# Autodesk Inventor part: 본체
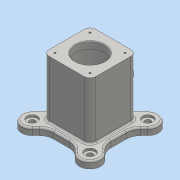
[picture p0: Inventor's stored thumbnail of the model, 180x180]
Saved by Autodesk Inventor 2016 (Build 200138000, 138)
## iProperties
Created: 2019-11
Part Number: 본체
Material: 일반
Document SubType Name: Modeling
Designer: user
Density: 1 g/cm^3
Appearance: 기본값
Author: user
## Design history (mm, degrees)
sketch "스케치2"
  geometry: L1 (-49, 49)-(49, 49); L2 (49, 49)-(49, -49); L3 (49, -49)-(-49, -49); L4 (-49, -49)-(-49, 49); L5 (-49, 49)-(49, -49); L6 (49, 49)-(-49, -49); L7 (49.497, -49.497)-(-49.497, 49.497); L8 (62.225, -36.77)-(-36.77, 62.225); L9 (-62.225, 36.77)-(36.77, -62.225); L10 (-49.497, -49.497)-(49.497, 49.497); L11 (-36.77, -62.225)-(62.225, 36.77); L12 (36.77, 62.225)-(-62.225, -36.77); A1 r 70 centre (0, 0) between (-49.497, 49.497) and (49.497, 49.497); A2 r 18 centre (49.497, -49.497) between (36.77, -62.225) and (62.225, -36.77); A3 r 18 centre (-49.497, 49.497) between (-36.77, 62.225) and (-62.225, 36.77); A4 r 18 centre (-49.497, -49.497) between (-62.225, -36.77) and (-36.77, -62.225); A5 r 18 centre (49.497, 49.497) between (62.225, 36.77) and (36.77, 62.225); 1 further point
  constraints: 28 end point, 10 point on circle, 8 tangent, 5 centre point, 4 midpoint, 4 parallel, 2 point on line, 1 coincident, 1 horizontal, 1 perpendicular
  dimensions: "d5" = 98 distance of L1.start L1.end; "d6" = 98 distance of L3.end L1.start; "d7" = 140 diameter of A1; "d8" = 36 diameter of A3; "d9" = 36 diameter of A5
extrude "돌출1" new body sketch "스케치2" distance "d10" = 12; taper "d11" = 0 deg
sketch "스케치3"
  geometry: L1 (-40, 40)-(40, 40); L2 (40, 40)-(40, -40); L3 (40, -40)-(-40, -40); L4 (-40, -40)-(-40, 40); L5 (-40, 40)-(40, -40); L6 (40, 40)-(-40, -40); 1 further point
  constraints: 12 end point, 2 midpoint, 2 parallel, 1 horizontal, 1 perpendicular
  dimensions: "d12" = 80 distance of L1.start L1.end; "d13" = 80 distance of L3.end L1.start
extrude "돌출2" join sketch "스케치3" distance "d14" = 98; taper "d15" = 0 deg
sketch "스케치4"
  geometry: A1 r 18 centre (-49.497, 49.497) between (-36.77, 62.225) and (-62.225, 36.77) reference; 2 further points
  constraints: 1 coincident
hole "구멍1" sketch "스케치4" at (-49.497, 49.497) diameter "d16" = 10; stored, may be unused: countersink angle "d20" = 90 deg, drill point angle "d22" = 118 deg; dims "d17" = 6, "d18" = 18, "d19" = 4, "d21" = 8
sketch "스케치5"
  geometry: A1 r 18 centre (49.497, 49.497) between (62.225, 36.77) and (36.77, 62.225) reference; A2 r 18 centre (49.497, -49.497) between (36.77, -62.225) and (62.225, -36.77) reference; A3 r 18 centre (-49.497, -49.497) between (-62.225, -36.77) and (-36.77, -62.225) reference; 4 further points
  constraints: 3 coincident
hole "구멍2" sketch "스케치5" at (49.497, 49.497), (49.497, -49.497), (-49.497, -49.497) diameter "d23" = 10; stored, may be unused: countersink angle "d27" = 90 deg, drill point angle "d29" = 118 deg; dims "d24" = 6, "d25" = 18, "d26" = 4, "d28" = 8
sketch "스케치6"
  geometry: C1 r 25 at (0, 0); 1 further point
  constraints: 1 centre point, 1 coincident
  dimensions: "d30" = 50 diameter of C1
extrude "돌출3" cut sketch "스케치6" distance "d31" = 225.75; taper "d32" = 0 deg
node "작업 평면1"
sketch "스케치7"
  geometry: C1 r 35 at (0, 0); 1 further point
  constraints: 1 centre point, 1 coincident
  dimensions: "d34" = 70 diameter of C1
extrude "돌출4" cut sketch "스케치7" distance "d35" = 86; taper "d36" = 0 deg
node "작업 평면2"
sketch "스케치8"
  geometry: C1 r 20 at (0, 61); 1 further point
  constraints: 1 centre point, 1 vertical alignment
  dimensions: "d38" = 61 distance of point (0, 0) C1.centre; "d39" = 40 diameter of C1
extrude "돌출5" join sketch "스케치8" stored distance "d40" = 86; taper "d41" = 0 deg
sketch "스케치9"
  geometry: C1 r 20 at (0, 0) reference; 2 further points
  constraints: 2 coincident
hole "구멍3" sketch "스케치9" at (0, 0) diameter "d42" = 25; stored, may be unused: countersink angle "d46" = 90 deg, drill point angle "d48" = 118 deg; dims "d43" = 6, "d44" = 30, "d45" = 8, "d47" = 55
sketch "스케치10"
  geometry: L1 (-30, 30)-(30, 30); L2 (30, 30)-(30, -30); L3 (30, -30)-(-30, -30); L4 (-30, -30)-(-30, 30); L5 (-30, 30)-(30, -30); L6 (30, 30)-(-30, -30); C1 r 5 at (-49.497, 49.497) reference; A1 r 18 centre (-49.497, 49.497) between (-36.77, 62.225) and (-62.225, 36.77) reference; 5 further points
  constraints: 12 end point, 4 coincident, 2 midpoint, 2 parallel, 1 horizontal, 1 perpendicular
  dimensions: "d49" = 60 distance of L1.start L1.end; "d50" = 60 distance of L1.end L2.end
hole "구멍4" sketch "스케치10" at (-30, 30), (30, 30), (30, -30), (-30, -30) diameter "d51" = 3.242; stored, may be unused: countersink angle "d55" = 90 deg, drill point angle "d57" = 118 deg; dims "d52" = 8, "d53" = 30, "d54" = 8, "d56" = 10
node "작업 평면3"
fillet "모깎기1" dims "d59" = 25
fillet "모깎기2" dims "d60" = 10
fillet "모깎기3" dims "d61" = 3
fillet "모깎기4" dims "d62" = 3
chamfer "모따기1" distance "d63" = 1; stored, may be unused: second distance "d64" = 2, angle "d65" = 45 deg
fillet "모깎기5" dims "d66" = 3
chamfer "모따기2" distance "d67" = 1; stored, may be unused: second distance "d68" = 2, angle "d69" = 45 deg
fillet "모깎기6" dims "d70" = 3
chamfer "모따기3" distance "d71" = 1; stored, may be unused: second distance "d72" = 2, angle "d73" = 45 deg
sketch "스케치11"
  geometry: L1 (60, 0)-(0, 0) reference; L2 (16.811, 110)-(43.189, 110) reference; 3 further points
  constraints: 1 midpoint, 1 vertical alignment, 1 other
  dimensions: "d74" = 10 distance from line of L1 point (30, 10)
feature "엠보싱1" sketch "스케치11" dims "d5" = 98, "d6" = 98, "d7" = 140, "d8" = 36, "d9" = 36, "d75" = 0.5, "d76" = 0
node "솔리드1"
mirror "대칭1"
other parameters: "d33" = 12, "d37" = 55, "d58" = 55
